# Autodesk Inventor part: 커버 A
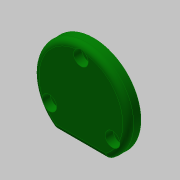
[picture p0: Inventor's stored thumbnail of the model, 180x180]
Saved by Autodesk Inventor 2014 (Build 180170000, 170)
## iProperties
Created: 2020-04
Part Number: 커버 A
Material: 알루미늄 6061
Document SubType Name: Modeling
Designer: mduedu
Density: 2.71 g/cm^3
Mass: 30.8964 g
Surface Area: 61.0159 cm^2
Volume: 11.4009 cm^3
Appearance: 진녹색
Author: mduedu
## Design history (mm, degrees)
sketch "스케치1"
  geometry: C1 r 26 at (0, 0); 1 further point
  constraints: 1 centre point, 1 coincident
  dimensions: "d0" = 52 diameter of C1
extrude "돌출1" new body sketch "스케치1" distance "d1" = 7; taper "d2" = 0 deg
sketch "스케치2"
  geometry: L1 (-14.62, -21.5)-(14.62, -21.5); A1 r 26 centre (0, 0) between (-14.62, -21.5) and (14.62, -21.5) reference; 1 further point
  constraints: 2 end point, 2 point on circle, 1 horizontal
  dimensions: "d3" = 21.5 distance from line of L1 point (0, 0)
extrude "돌출2" cut sketch "스케치2" stored distance "d4" = 7; taper "d5" = 0 deg
fillet "모깎기1" dims "d6" = 3
fillet "모깎기2" dims "d7" = 3
sketch "스케치3" dims "d8" = 40
  geometry: 3 further points
  constraints: 2 vertical alignment, 1 coincident, 2 other
hole "구멍1" sketch "스케치3" at (0, 20) diameter "d9" = 4.5; stored, may be unused: countersink angle "d13" = 90 deg, drill point angle "d15" = 118 deg; dims "d10" = 6, "d11" = 8, "d12" = 4.4, "d14" = 8
sketch "스케치4"
  geometry: C1 r 16 at (0, 0); 1 further point
  constraints: 1 centre point, 1 coincident
  dimensions: "d19" = 32 diameter of C1
extrude "돌출3" join sketch "스케치4" distance "d20" = 3; taper "d21" = 0 deg
sketch "스케치5"
  geometry: C1 r 14 at (0, 0); 1 further point
  constraints: 1 centre point, 1 coincident
  dimensions: "d22" = 28 diameter of C1
extrude "돌출4" cut sketch "스케치5" distance "d23" = 7; taper "d24" = 0 deg
fillet "모깎기3" dims "d25" = 3
chamfer "모따기1" distance "d26" = 0.5; stored, may be unused: second distance "d27" = 2, angle "d28" = 45 deg
node "솔리드1"
pattern_circular "원형 패턴1" dims angle "d17" = 360 deg
node "투영된 루프1"
